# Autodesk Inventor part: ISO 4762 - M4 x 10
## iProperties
Comments: To add or edit properties for Autodesk Inventor files, use iProperties.
Created: 2004-08
Part Number: ISO 4762 - M4 x 10
Vendor: Autodesk Inc.
Document SubType Name: Modeling
Designer: John Blackburn
Material: Default
Description: Hexagon Socket Head Cap Screw
Standard: ISO 4762
Size Designation: M4 x 10
Alert: To add or edit properties for Autodesk Inventor files, use iProperties.
Control State: 0
Master: False
Checked Out: False
Shininess: 64.0
Length Units: 11269
Angle Units: 11279
Time Units: 11290
Mass Units: 11283
Length Display Precision: 3
Angle Display Precision: 2
Compacted: True
EGR: 1
Density: 0.0
Volumn: 0.0
Area: 0.0
PropertySet Name: Model Information
Author: John Blackburn
Revision Number: 8
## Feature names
1. Body [Revolution]
2. Slot [Extrusion]
3. Fillet1
4. Chamfer1
